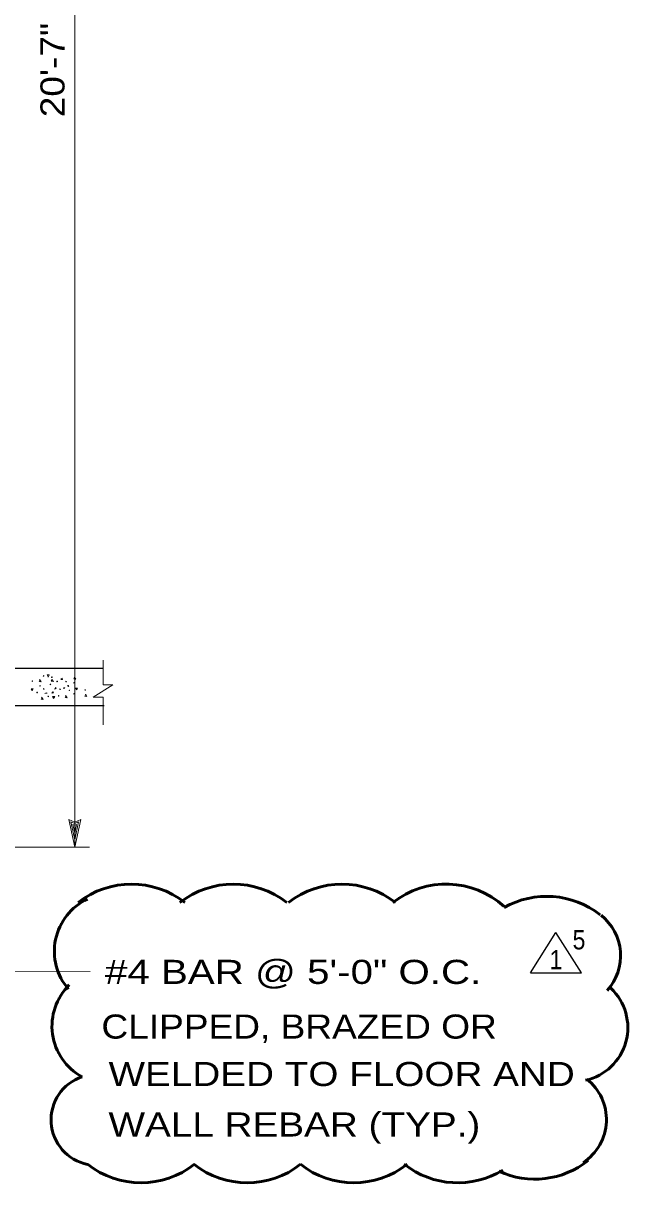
# Model space of a CAD drawing. Extents: x -28.1 to 13.9, y -16.1 to 13.9.
# Drawn here: x 0.04 to 3.17, y 1.34 to 7.35 of the extents above; entities that cross this region are included whole.
import ezdxf
from ezdxf.enums import TextEntityAlignment as Align

# ---------------------------------------------------------------- set-up
doc = ezdxf.new("R2010")
doc.units = 0
doc.header["$LTSCALE"] = 0.05
for name, color, linetype, lineweight in [('1', 7, 'Continuous', 13), ('2', 7, 'Continuous', 13), ('5', 7, 'Continuous', 53)]:
    doc.layers.add(name, color=color, linetype=linetype, lineweight=lineweight)

msp = doc.modelspace()

# ---------------------------------------------------------------- linework, layer by layer
at = {"layer": '1'}
for p, q in [((0.30296, 3.07869), (0.30296, 10.57569)), ((0.45096, 3.92069), (0.45096, 4.04869)), ((0.39896, 3.85669), (0.49996, 3.92069)), ((0.45096, 3.92069), (0.49996, 3.92069)), ((0.39896, 3.85669), (0.45096, 3.85669)), ((0.45096, 3.71369), (0.45096, 3.85669)), ((0.30296, 3.07869), (0.27196, 3.22269)), ((0.30296, 3.11569), (0.28296, 3.20969)), ((0.28296, 3.20969), (0.30296, 3.20069)), ((0.30296, 3.15169), (0.29296, 3.19669)), ((0.29296, 3.19669), (0.30296, 3.19269)), ((0.30296, 3.07869), (0.33396, 3.22269)), ((0.30296, 3.11569), (0.32296, 3.20969)), ((0.30296, 3.20069), (0.32296, 3.20969)), ((0.30296, 3.15169), (0.31196, 3.19669)), ((0.30296, 3.19269), (0.31196, 3.19669)), ((-1.03804, 3.07869), (0.37996, 3.07869))]:
    msp.add_line(p, q, dxfattribs=at)
at = {"layer": '1', "lineweight": 25}
for p, q in [((-1.91804, 4.00669), (0.45096, 4.00669)), ((-1.30504, 3.81269), (0.45596, 3.81269)), ((2.66606, 2.42627), (2.79906, 2.63527)), ((2.93206, 2.42627), (2.79906, 2.63527)), ((2.66606, 2.42627), (2.93206, 2.42627))]:
    msp.add_line(p, q, dxfattribs=at)
at = {"layer": '1'}
for points in [[(-1.59712, 3.89047), (-0.28558, 2.43598), (0.38318, 2.43322)], [(0.27196, 3.22269), (0.30296, 3.20869), (0.33396, 3.22269)]]:
    msp.add_lwpolyline(points, dxfattribs=at)
at = {"layer": '1', "lineweight": 53}
for centre, radius, start, end in [((0.49706, 2.53799), 0.29984, 115.29885, 220.95318), ((2.86683, 2.51504), 0.26755, 317.68912, 51.70528), ((0.48476, 2.15024), 0.29984, 134.56627, 241.26872), ((2.89122, 2.14292), 0.28037, 282.61276, 46.65644), ((0.41551, 1.66417), 0.23537, 108.5515, 258.7583), ((2.793, 1.66568), 0.26755, 303.53385, 51.70528)]:
    msp.add_arc(centre, radius, start, end, dxfattribs=at)
at = {"layer": '2'}
msp.add_line((0.23096, 3.95069), (0.23696, 3.95569), dxfattribs=at)
for points in [[(0.16496, 3.96269), (0.15996, 3.97169), (0.17096, 3.97169), (0.16496, 3.96069)], [(0.12396, 3.94769), (0.11896, 3.93769), (0.12896, 3.93669), (0.12096, 3.94769)], [(0.18596, 3.94869), (0.18096, 3.93869), (0.19196, 3.93769), (0.18396, 3.94869)], [(0.23696, 3.95569), (0.23896, 3.94869), (0.23096, 3.94869)], [(0.26396, 3.91569), (0.26896, 3.91769), (0.27196, 3.91169), (0.26396, 3.91469)], [(0.30396, 3.96069), (0.29896, 3.95069), (0.30896, 3.94969), (0.30096, 3.96069)], [(0.08196, 3.89169), (0.07696, 3.89969), (0.08796, 3.89969), (0.08196, 3.88969)], [(0.13396, 3.85569), (0.12896, 3.84569), (0.13896, 3.84469), (0.13096, 3.85569)], [(0.15096, 3.87669), (0.15596, 3.87969), (0.15996, 3.87669), (0.14796, 3.87469)], [(0.19296, 3.85069), (0.18796, 3.85969), (0.19896, 3.85969), (0.19296, 3.84969)], [(0.24396, 3.90269), (0.24696, 3.90669), (0.25196, 3.90269), (0.24496, 3.90169)], [(0.25796, 3.86469), (0.25296, 3.85469), (0.26296, 3.85369), (0.25496, 3.86469)], [(0.31196, 3.89569), (0.30696, 3.90369), (0.31796, 3.90369), (0.31196, 3.89369)], [(0.36096, 3.87169), (0.35596, 3.86169), (0.36596, 3.86069), (0.35896, 3.87169)]]:
    msp.add_lwpolyline(points, dxfattribs=at)
for points in [[(0.18396, 3.87669), (0.18896, 3.88469), (0.19196, 3.87869)], [(0.19896, 3.89769), (0.20396, 3.90669), (0.20696, 3.90069)]]:
    msp.add_lwpolyline(points, close=True, dxfattribs=at)
for centre in [(0.08296, 3.93981), (0.12271, 3.91456), (0.14121, 3.96656), (0.17646, 3.92281), (0.18396, 3.95981), (0.21171, 3.93806), (0.25796, 3.93706), (0.29921, 3.93131), (0.10746, 3.88081), (0.14196, 3.89931), (0.16546, 3.86056), (0.21946, 3.86306), (0.22696, 3.89756), (0.27496, 3.89181), (0.30021, 3.87406), (0.35746, 3.89356)]:
    msp.add_circle(centre, 0.00162, dxfattribs=at)
at = {"layer": '5'}
for centre, start, end in [((0.59721, 2.43873), 51.81631, 128.18369), ((1.12587, 2.43873), 51.81631, 128.18369), ((1.68883, 2.43873), 51.81631, 128.18369), ((2.22935, 2.43873), 47.81241, 128.18369), ((2.7507, 2.37524), 51.81631, 119.52336), ((2.68917, 1.80463), 245.42409, 308.18369), ((0.64668, 1.78558), 231.81631, 308.18369), ((1.19769, 1.78558), 231.81631, 308.18369), ((1.75017, 1.78558), 231.81631, 308.18369), ((2.28931, 1.78558), 231.81631, 301.51936)]:
    msp.add_arc(centre, 0.44809, start, end, dxfattribs=at)

# ---------------------------------------------------------------- texts
at = {"layer": '1', "width": 1.15}
msp.add_text('20\'-7"', height=0.125, rotation=90, dxfattribs=at).set_placement((0.24996, 7.10902), align=Align.CENTER)
at = {"layer": '1', "width": 0.9}
for s, p in [('5', (2.9184, 2.54827)), ('1', (2.7994, 2.44527))]:
    msp.add_text(s, height=0.1, dxfattribs=at).set_placement(p, align=Align.CENTER)
at = {"layer": '1'}
for s, width, p in [('#4 BAR @ 5\'-0" O.C.', 1.25, (0.45974, 2.36903)), ('CLIPPED, BRAZED OR ', 1.15, (0.44127, 2.08544)), ('WELDED TO FLOOR AND', 1.2, (0.4782, 1.83939)), ('WALL REBAR (TYP.)', 1.2, (0.4782, 1.57746))]:
    msp.add_text(s, height=0.125, dxfattribs=dict(at, width=width)).set_placement(p)

doc.saveas('drawing.dxf')
